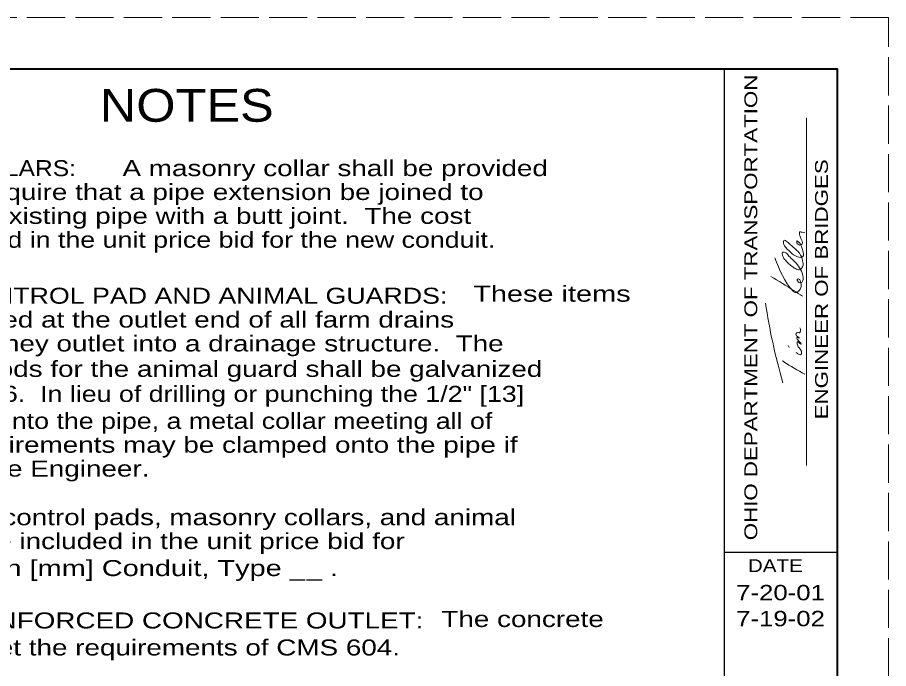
# Model space of a CAD drawing. Extents: x 1083.1 to 1117.1, y 697.4 to 741.4.
# Drawn here: x 1108.64 to 1117.13, y 735.01 to 741.35 of the extents above; entities that cross this region are included whole.
import ezdxf
from ezdxf.enums import TextEntityAlignment as Align

# ---------------------------------------------------------------- set-up
doc = ezdxf.new("R2010")
doc.units = 0
doc.header["$LTSCALE"] = 0.062
doc.linetypes.add('LONG_DASHED', pattern=[7.5, 6, -1.5])
doc.layers.add('1', color=7, linetype='Continuous', lineweight=13)

msp = doc.modelspace()

# ---------------------------------------------------------------- linework, layer by layer
at = {"layer": '1', "lineweight": 25}
for p, q in [((1085.12642, 740.85408), (1116.62642, 740.85408)), ((1115.52642, 719.85408), (1115.52642, 740.85408)), ((1116.62642, 740.85408), (1116.62642, 719.85408)), ((1116.62642, 736.13825), (1115.52642, 736.13825))]:
    msp.add_line(p, q, dxfattribs=at)
at = {"layer": '1'}
for p, q in [((1116.32517, 736.98508), (1116.32517, 740.37517)), ((1116.15767, 738.136), (1116.1475, 738.15525))]:
    msp.add_line(p, q, dxfattribs=at)
at = {"layer": '1', "linetype": 'LONG_DASHED'}
msp.add_lwpolyline([(1083.12642, 719.35408), (1117.12642, 719.35408), (1117.12642, 741.35408), (1083.12642, 741.35408)], close=True, dxfattribs=at)
at = {"layer": '1', "lineweight": 40}
msp.add_lwpolyline([(1085.12642, 740.85408), (1116.62642, 740.85408), (1116.62642, 719.85408), (1085.12642, 719.85408)], close=True, dxfattribs=at)
msp.add_lwpolyline([(1085.12642, 740.85408), (1116.62642, 740.85408), (1116.62642, 719.85408), (1085.12642, 719.85408)], close=True, dxfattribs=at)
at = {"layer": '1'}
for points in [[(1116.01825, 739.01108), (1116.20142, 738.68275), (1116.21658, 738.67217), (1116.22675, 738.67217), (1116.25867, 738.69583), (1116.27375, 738.73), (1116.26875, 738.78125), (1116.25183, 738.80308), (1116.23833, 738.80308), (1116.23658, 738.79008), (1116.24675, 738.77492), (1116.26025, 738.7665), (1116.27533, 738.7665), (1116.2905, 738.78808), (1116.29392, 738.80742), (1116.28367, 738.86275), (1116.20142, 738.98317), (1116.15592, 739.02783), (1116.119, 739.06242), (1116.09383, 739.06458), (1116.09558, 739.026), (1116.12075, 738.98725), (1116.188, 738.92492), (1116.23008, 738.8995), (1116.26375, 738.895), (1116.28708, 738.921), (1116.29392, 738.95517), (1116.28883, 738.98092), (1116.25867, 739.05408), (1116.22842, 739.08608), (1116.16783, 739.1395), (1116.13917, 739.16533), (1116.10567, 739.18058), (1116.10225, 739.15258), (1116.11233, 739.12675), (1116.1695, 739.06683), (1116.24017, 739.01958), (1116.29217, 739.02192), (1116.2905, 739.07958), (1116.27867, 739.1225), (1116.26533, 739.14825), (1116.25517, 739.159), (1116.23175, 739.174), (1116.2335, 739.15692), (1116.26875, 739.13542), (1116.28367, 739.14617), (1116.27058, 739.19983), (1116.262, 739.22775), (1116.25867, 739.24042), (1116.25867, 739.25325), (1116.25867, 739.26192), (1116.28367, 739.25975), (1116.30908, 739.25975)], [(1115.97942, 738.82883), (1116.20317, 738.69133), (1116.28883, 738.63567)], [(1116.09567, 737.79183), (1115.997, 738.18708), (1115.92575, 738.56942)], [(1116.22675, 738.09075), (1116.235, 738.08008), (1116.27217, 738.06717), (1116.27692, 738.09958), (1116.25183, 738.136), (1116.23658, 738.17225), (1116.23658, 738.1915), (1116.25183, 738.18525), (1116.262, 738.17442), (1116.27217, 738.17008), (1116.2485, 738.20225), (1116.23658, 738.21725), (1116.2335, 738.23458), (1116.25692, 738.228), (1116.2485, 738.23667), (1116.22333, 738.2645), (1116.2335, 738.27967), (1116.25025, 738.28167), (1116.25867, 738.27967), (1116.26875, 738.301), (1116.262, 738.32892)], [(1116.31083, 737.87625), (1116.10567, 737.99625), (1116.09008, 738.00667)]]:
    msp.add_spline(points, degree=3, dxfattribs=at)

# ---------------------------------------------------------------- texts
at = {"layer": '1', "width": 1.3}
for s, p in [('OHIO DEPARTMENT OF TRANSPORTATION', (1115.84633, 738.52633)), ('ENGINEER OF BRIDGES', (1116.53467, 738.70312))]:
    msp.add_text(s, height=0.125, rotation=90, dxfattribs=at).set_placement(p, align=Align.CENTER)
at = {"layer": '1'}
for s, height, width, p in [('NOTES', 0.32, 1.15, (1109.43983, 740.33683)), ('MASONRY COLLARS:', 0.156, 1.15, (1106.74217, 739.8065)), ('A masonry collar shall be provided', 0.156, 1.3, (1109.66108, 739.8065)), ('where plans require that a pipe extension be joined to', 0.156, 1.3, (1106.74217, 739.57383)), ('the end of an existing pipe with a butt joint.  The cost', 0.156, 1.3, (1106.74217, 739.34117)), ('shall be included in the unit price bid for the new conduit.', 0.156, 1.25, (1106.74217, 739.10842)), ('EROSION CONTROL PAD AND ANIMAL GUARDS:', 0.156, 1.25, (1106.74217, 738.56275)), ('These items ', 0.156, 1.35, (1113.07883, 738.58225)), ('shall be provided at the outlet end of all farm drains', 0.156, 1.3, (1106.74217, 738.33008)), ('except where they outlet into a drainage structure.  The', 0.156, 1.3, (1106.74217, 738.09733)), ('steel bolts or rods for the animal guard shall be galvanized', 0.156, 1.3, (1106.74217, 737.8495)), ('per CMS 710.06.  In lieu of drilling or punching the 1/2" [13]', 0.156, 1.25, (1106.74217, 737.60567)), ('diameter holes into the pipe, a metal collar meeting all of', 0.156, 1.25, (1106.74217, 737.34242)), ('the above requirements may be clamped onto the pipe if ', 0.156, 1.3, (1106.74217, 737.10975)), ('approved by the Engineer.', 0.156, 1.3, (1106.74217, 736.87708)), ('          Erosion control pads, masonry collars, and animal', 0.156, 1.3, (1106.74217, 736.4035)), ('guards shall be included in the unit price bid for', 0.156, 1.3, (1106.74217, 736.17083)), ('    Item 603 - __ inch [mm] Conduit, Type __ .', 0.156, 1.35, (1106.1105, 735.9075)), ('The concrete', 0.156, 1.3, (1112.76842, 735.41075)), ('outlet shall meet the requirements of CMS 604.', 0.156, 1.3, (1106.698, 735.13333))]:
    msp.add_text(s, height=height, dxfattribs=dict(at, width=width)).set_placement(p)
for s, height, width, p in [('DATE', 0.125, 1.2, (1116.02312, 735.94683)), ('7-20-01', 0.15, 1.25, (1116.07346, 735.67133)), ('PRECAST REINFORCED CONCRETE OUTLET:', 0.156, 1.3, (1109.60979, 735.39675)), ('7-19-02', 0.15, 1.25, (1116.07346, 735.41825))]:
    msp.add_text(s, height=height, dxfattribs=dict(at, width=width)).set_placement(p, align=Align.CENTER)

doc.saveas('drawing.dxf')
